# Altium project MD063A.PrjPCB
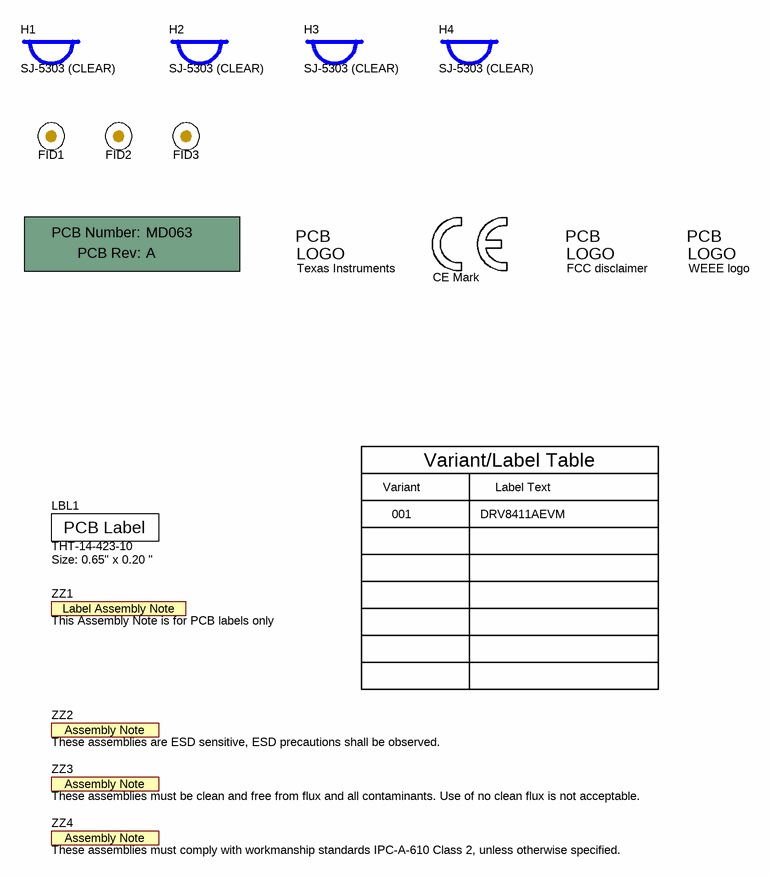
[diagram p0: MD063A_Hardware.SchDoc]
CopyrightYear: 2023; EVM_orderable: DRV8411AEVM; PCB_Layout: Pablo Armet; PCB_Rev: A; PRJ_Customer: Public Release; PRJ_Engineer: Pablo Armet; PRJ_Number: MD063; PRJ_Title: DRV8411AEVM; SCH_Rev: A; SVN: 0; TechSupport: http://www.ti.com/support; TID: N/A
3 sheets, 163 parts. Net scope: global (net labels, ports and power ports of the same name join across sheets).
Board file: MD063A_PCB.PcbDoc
Sheets:
  MD063A_Hardware.SchDoc
  MD063A_Sch.SchDoc
  ezFET.SchDoc

## Sheet MD063A_Hardware.SchDoc
size 431 x 279 mm; Date: Not shown in title block; ApprovedBy: Not shown in title block; CheckedBy: Not shown in title block; Author: Not shown in title block; CompanyName: Not shown in title block; Engineer: Not shown in title block; Organization: Not shown in title block; Address1: Not shown in title block; Address2: Not shown in title block; Address3: Not shown in title block; Address4: Not shown in title block; DocumentNumber: 3; Revision: Use project parameter SCH_Rev; SheetNumber: 3; SheetTotal: 3; PageSetup: Record=PageOptions¦CenterHorizontal=True¦CenterVertical=True¦PrintScale=1.00¦XCorrection=1.00¦YCorrection=1.00¦PrintKind=0¦BorderSize=5000000¦LeftOffset=0¦BottomOffset=0¦Orientation=2¦PaperLength=1000¦PaperWidth=1000¦Scale=100¦PaperSource=15¦PrintQuality=600¦MediaType=1¦DitherType=10¦PaperKind=Letter¦PrintScaleMode=1

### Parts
!PCB1  Printed Circuit Board  (value not drawn)  (mechanical)
FID1  Fiducial  [Fiducial10-20]  (value not drawn)
FID2  Fiducial  [Fiducial10-20]  (value not drawn)
FID3  Fiducial  [Fiducial10-20]  (value not drawn)
H1  SJ-5303 (CLEAR)  [Bumpon_SJ5003Transparent]
H2  SJ-5303 (CLEAR)  [Bumpon_SJ5003Transparent]
H3  SJ-5303 (CLEAR)  [Bumpon_SJ5003Transparent]
H4  SJ-5303 (CLEAR)  [Bumpon_SJ5003Transparent]
LBL1  THT-14-423-10  Note: Size: 0.65" x 0.20 "  [Label_650x200]
Logo1  Texas Instruments  [TI_Stacked_Overlay_Small]  (no BOM)
Logo2  CE Mark  [CE_Mark_5mm]  (no BOM)
Logo3  FCC disclaimer  [FCC_disclaimer]  (no BOM)
Logo4  WEEE logo  [WEEE_Minimum]  (no BOM)
ZZ1  This Assembly Note is for PCB labels only  [AssemblyNoteLabel]  (no BOM)
ZZ2  These assemblies are ESD sensitive, ESD precautions shall be observed.  [AssemblyNote]  (no BOM)
ZZ3  These assemblies must be clean and free from flux and all contaminants. Use of no clean flux is not acceptable.  [AssemblyNote]  (no BOM)
ZZ4  These assemblies must comply with workmanship standards IPC-A-610 Class 2, unless otherwise specified.  [AssemblyNote]  (no BOM)

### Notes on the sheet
- Variant
- Variant/Label Table
- Label Text
- 001
- DRV8411AEVM

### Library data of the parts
!PCB1 = CMP-0003618-2: Manufacturer: Any; PartNumber: MD063
FID1-FID3 = CMP-0077181-1: Fiducial mark.  There is nothing to buy or mount.
H1-H4 = CMP-0003620-1: Bumpon, Hemisphere, 0.44 X 0.20, Clear; Manufacturer: 3M
LBL1 = CMP-0003625-1: Thermal Transfer Printable Labels, 0.650" W x 0.200" H - 10,000 per roll; Manufacturer: Brady; CompType: Label
Logo1 = CMP-0074838-1: Texas Instrument Corporate Signature; SymbolCreator: a0412235; Lib Reference: TI_Logo; Library Reference: Logo
Logo2 = CMP-0074844-1: SymbolCreator: a0412235
Logo3 = CMP-0074847-1: FCC_disclaimer; Library Reference: Logo
Logo4 = CMP-0074769-3: Manufacturer: Texas Instruments; CompType: IC; AEC Category: Q200
ZZ1 = CMP-0003616-3
ZZ2 = CMP-0077236-1
ZZ3 = CMP-0077237-1
ZZ4 = CMP-0077238-1

## Sheet MD063A_Sch.SchDoc
size 431 x 279 mm; Date: Not shown in title block; ApprovedBy: Not shown in title block; CheckedBy: Not shown in title block; Author: Not shown in title block; CompanyName: Not shown in title block; Engineer: Not shown in title block; Organization: Not shown in title block; Address1: Not shown in title block; Address2: Not shown in title block; Address3: Not shown in title block; Address4: Not shown in title block; DocumentNumber: 2; Revision: Use project parameter SCH_Rev; SheetNumber: 2; SheetTotal: 3; PageSetup: Record=PageOptions¦CenterHorizontal=True¦CenterVertical=True¦PrintScale=1.00¦XCorrection=1.00¦YCorrection=1.00¦PrintKind=0¦BorderSize=5000000¦LeftOffset=0¦BottomOffset=0¦Orientation=2¦PaperLength=1000¦PaperWidth=1000¦Scale=100¦PaperSource=15¦PrintQuality=600¦MediaType=1¦DitherType=10¦PaperKind=Letter¦PrintScaleMode=1
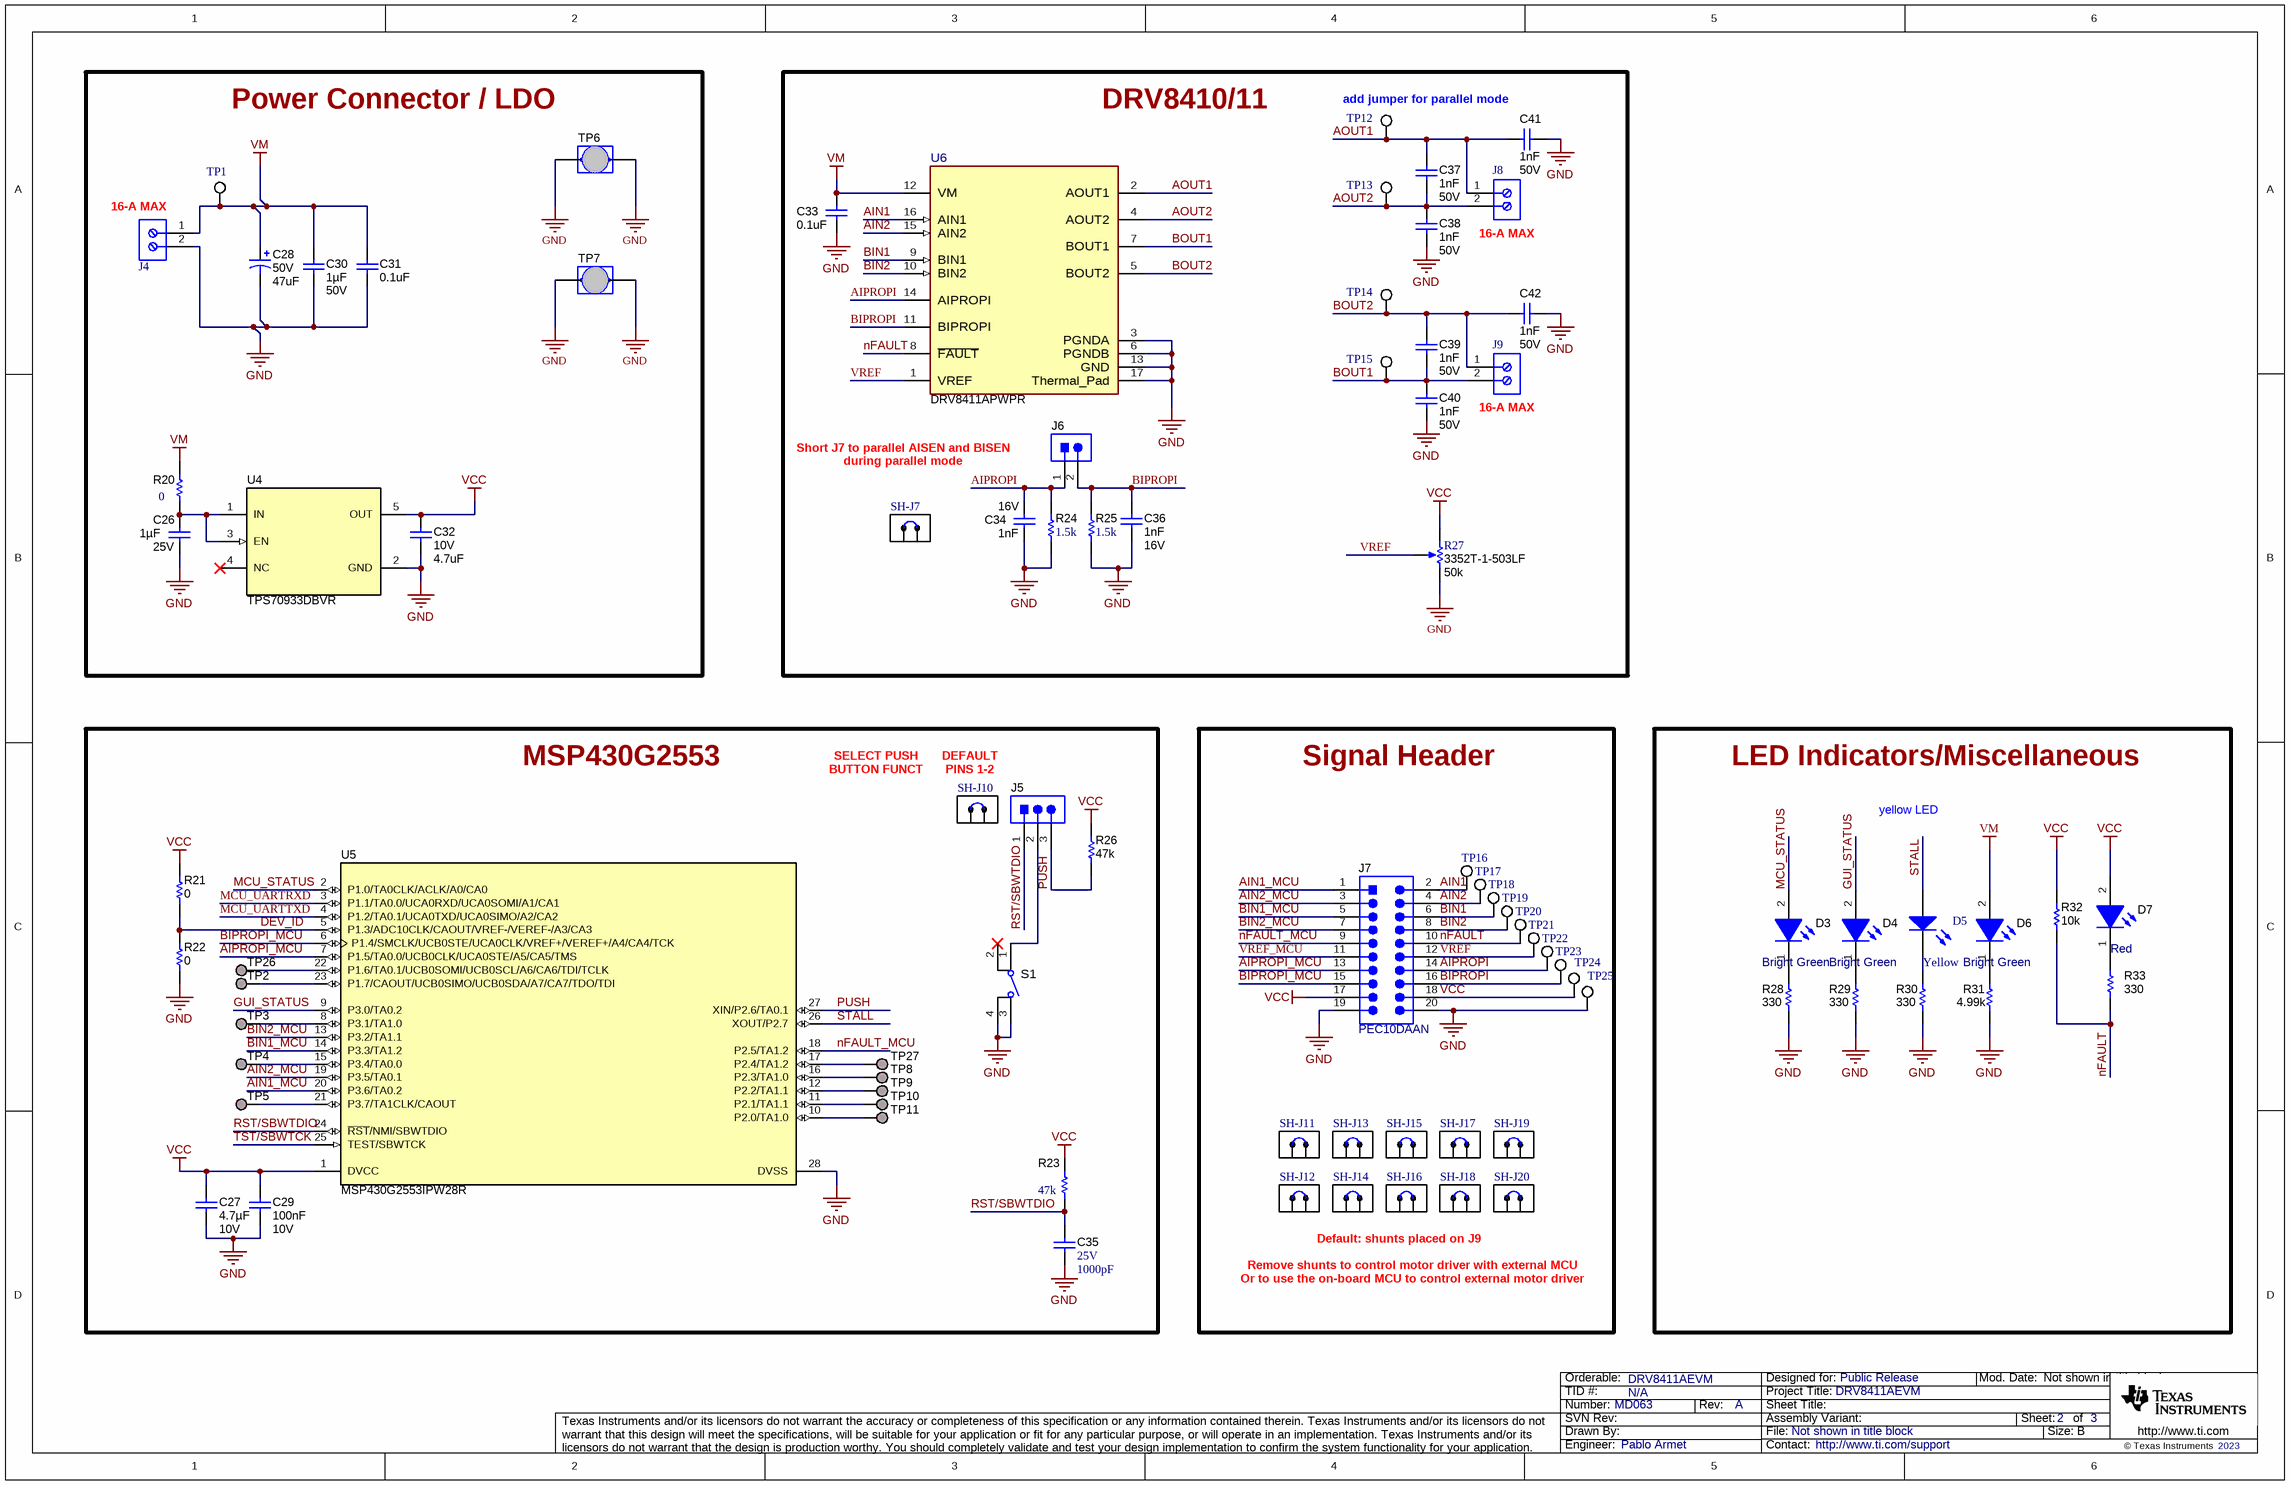
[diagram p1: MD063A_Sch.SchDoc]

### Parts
C26  Cap_F: 1µF  VDC_V: 25V  [0603]  (hidden comment: 885012206076)
C27  Cap_F: 4.7µF  VDC_V: 10V  [0805L]  (hidden comment: 885012207025)
C28  VDC_V: 50V  ValueDisplayed: 47uF  [WCAP-ASLI_630x770]  (hidden comment: 865080645012)
C29  Cap_F: 100nF  VDC_V: 10V  [0603]  (hidden comment: 885012206020)
C30  Cap_F: 1µF  VDC_V: 50V  [0805L]  (hidden comment: 885012207103)
C31  ValueDisplayed: 0.1uF  [0603L]  (hidden comment: 885012206095)
C32  VDC_V: 10V  ValueDisplayed: 4.7uF  [0603]  (hidden comment: GRM188R61A475ME15)
C33  ValueDisplayed: 0.1uF  [0603L]  (hidden comment: 885012206095)
C34  Cap_F: 1nF  VDC_V: 16V  [0603L]  (hidden comment: 885012206034)
C35  VDC_V: 25V  ValueDisplayed: 1000pF  [0603S]  (hidden comment: GRM1885C1E102JA01D)
C36  Cap_F: 1nF  VDC_V: 16V  [0603L]  (hidden comment: 885012206034)
C37  Cap_F: 1nF  VDC_V: 50V  [0603L]  (hidden comment: 885012206083)
C38  Cap_F: 1nF  VDC_V: 50V  [0603L]  (hidden comment: 885012206083)
C39  Cap_F: 1nF  VDC_V: 50V  [0603L]  (hidden comment: 885012206083)
C40  Cap_F: 1nF  VDC_V: 50V  [0603L]  (hidden comment: 885012206083)
C41  Cap_F: 1nF  VDC_V: 50V  [0603L]  (hidden comment: 885012206083)
C42  Cap_F: 1nF  VDC_V: 50V  [0603L]  (hidden comment: 885012206083)
D3  value Bright Green  [WL-SMCW_Green_0805]  (hidden comment: 150080VS75000)
D4  value Bright Green  [WL-SMCW_Green_0805]  (hidden comment: 150080VS75000)
D5  Yellow  [0805_A]
D6  value Bright Green  [WL-SMCW_Green_0805]  (hidden comment: 150080VS75000)
D7  value Red  [WL-SMCW_RED_0805]  (hidden comment: 150080SS75000)
J4  691101710002  [691101710002]  (value not drawn)
J5  61300311121  [WURTH_61300311121]  (value not drawn)
J6  61300211121  [WURTH_61300211121]  (value not drawn)
J7  PEC10DAAN  [SULLINS_PEC10DAAN]
J8  691101710002  [691101710002]  (value not drawn)
J9  691101710002  [691101710002]  (value not drawn)
R20  ValueDisplayed: 0  [0603L]  (hidden comment: ERJ-3GEY0R00V)
R21  value 0  [0603L]  (hidden comment: CRCW06030000Z0EA)
R22  value 0  [0603L]  (hidden comment: CRCW06030000Z0EA)
R23  ValueDisplayed: 47k  [0603S]  (hidden comment: RC0603JR-0747KL)
R24  ValueDisplayed: 1.5k  [0603S]  (hidden comment: CRCW06031K50JNEA)
R25  ValueDisplayed: 1.5k  [0603S]  (hidden comment: CRCW06031K50JNEA)
R26  value 47k  [0603L]  (hidden comment: CRCW060347K0JNEA)
R27  3352T-1-503LF  value 50k  [Bourns_3352T]
R28  value 330  [0603L]  (hidden comment: CRCW0603330RJNEA)
R29  value 330  [0603L]  (hidden comment: CRCW0603330RJNEA)
R30  value 330  [0603L]  (hidden comment: CRCW0603330RJNEA)
R31  value 4.99k  [0603L]  (hidden comment: CRCW06034K99FKEA)
R32  ValueDisplayed: 10k  [0603L]  (hidden comment: CRCW060310K0JNEA)
R33  value 330  [0603L]  (hidden comment: CRCW0603330RJNEA)
S1  FSM4JSMA  [SW_FSM4JSMA]  (value not drawn)
SH-J7  60900213421  [Wurth_60900213421]  (value not drawn)
SH-J10  60900213421  [Wurth_60900213421]  (value not drawn)
SH-J11  60900213421  [Wurth_60900213421]  (value not drawn)
SH-J12  60900213421  [Wurth_60900213421]  (value not drawn)
SH-J13  60900213421  [Wurth_60900213421]  (value not drawn)
SH-J14  60900213421  [Wurth_60900213421]  (value not drawn)
SH-J15  60900213421  [Wurth_60900213421]  (value not drawn)
SH-J16  60900213421  [Wurth_60900213421]  (value not drawn)
SH-J17  60900213421  [Wurth_60900213421]  (value not drawn)
SH-J18  60900213421  [Wurth_60900213421]  (value not drawn)
SH-J19  60900213421  [Wurth_60900213421]  (value not drawn)
SH-J20  60900213421  [Wurth_60900213421]  (value not drawn)
TP1  5016  [Testpoint_Keystone_Compact]  (value not drawn)
TP2  TP_H0.45P0.75  [TP_H045P075]  (value not drawn)  (no BOM)
TP3  TP_H0.45P0.75  [TP_H045P075]  (value not drawn)  (no BOM)
TP4  TP_H0.45P0.75  [TP_H045P075]  (value not drawn)  (no BOM)
TP5  TP_H0.45P0.75  [TP_H045P075]  (value not drawn)  (no BOM)
TP6  CMP-0075110-1  [Harwin_D3082-05]  (value not drawn)
TP7  CMP-0075110-1  [Harwin_D3082-05]  (value not drawn)
TP8  TP_H0.45P0.75  [TP_H045P075]  (value not drawn)  (no BOM)
TP9  TP_H0.45P0.75  [TP_H045P075]  (value not drawn)  (no BOM)
TP10  TP_H0.45P0.75  [TP_H045P075]  (value not drawn)  (no BOM)
TP11  TP_H0.45P0.75  [TP_H045P075]  (value not drawn)  (no BOM)
TP12  5016  [Testpoint_Keystone_Compact]  (value not drawn)
TP13  5016  [Testpoint_Keystone_Compact]  (value not drawn)
TP14  5016  [Testpoint_Keystone_Compact]  (value not drawn)
TP15  5016  [Testpoint_Keystone_Compact]  (value not drawn)
TP16  5002  [Keystone5002]  (value not drawn)
TP17  5002  [Keystone5002]  (value not drawn)
TP18  5002  [Keystone5002]  (value not drawn)
TP19  5002  [Keystone5002]  (value not drawn)
TP20  5002  [Keystone5002]  (value not drawn)
TP21  5002  [Keystone5002]  (value not drawn)
TP22  5002  [Keystone5002]  (value not drawn)
TP23  5002  [Keystone5002]  (value not drawn)
TP24  5002  [Keystone5002]  (value not drawn)
TP25  5002  [Keystone5002]  (value not drawn)
TP26  TP_H0.45P0.75  [TP_H045P075]  (value not drawn)  (no BOM)
TP27  TP_H0.45P0.75  [TP_H045P075]  (value not drawn)  (no BOM)
U4  TPS70933DBVR  [DBV0005A_N]
U5  MSP430G2553IPW28R  [PW0028A_N]
U6  DRV8411APWPR  [PWP0016C-MFG]

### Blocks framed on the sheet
Power Connector / LDO: C26 C28 C30-C32 J4 R20 TP1 TP6 TP7 U4
DRV8410/11: C33 C34 C36-C42 J6 J8 J9 R24 R25 R27 SH-J7 TP12-TP15 U6
MSP430G2553: C27 C29 C35 J5 R21-R23 R26 S1 SH-J10 TP2-TP5 TP8-TP11 TP26 TP27 U5
Signal Header: J7 SH-J11-SH-J20 TP16-TP25
LED Indicators/Miscellaneous: D3-D7 R28-R33

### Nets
GND: C26.2 C27.2 C28.2(-) C29.2 C30.2 C31.2 C32.2 C33.2 C34.2 C35.2 C36.2 C38.2 C40.2 C41.2 C42.2 J4.2 J7.19 J7.20 R22.1 R24.1 R25.1 R27.3(CW) R28.1 R29.1 R30.1 R31.1 S1.3 S1.4 TP6.1 TP6.2 TP7.1 TP7.2 TP25.1 U4.2(GND) U5.28(DVSS) U6.3(PGNDA) U6.6(PGNDB) U6.13(GND) U6.17(Thermal_Pad)
VCC: C27.1 C29.1 C32.1 D7.2(A) J7.17 J7.18 R21.2 R23.2 R26.2 R27.1(CCW) R32.2 TP24.1 U4.5(OUT) U5.1(DVCC)
VM: C28.1(+) C30.1 C31.1 C33.1 D6.2(A) J4.1 R20.2 TP1.1 U6.12(VM)
AIN1: J7.2 TP16.1 U6.16(AIN1)
AIN1_MCU: J7.1 U5.20(P3.6/TA0.2)
AIN2: J7.4 TP17.1 U6.15(AIN2)
AIN2_MCU: J7.3 U5.19(P3.5/TA0.1)
AIPROPI: C34.1 J6.1 J7.14 R24.2 TP22.1 U6.14(AIPROPI)
AIPROPI_MCU: J7.13 U5.7(P1.5/TA0.0/UCB0CLK/UCA0STE/A5/CA5/TMS)
AOUT1: C37.1 C41.1 J8.1 TP12.1 U6.2(AOUT1)
AOUT2: C37.2 C38.1 J8.2 TP13.1 U6.4(AOUT2)
BIN1: J7.6 TP18.1 U6.9(BIN1)
BIN1_MCU: J7.5 U5.14(P3.3/TA1.2)
BIN2: J7.8 TP19.1 U6.10(BIN2)
BIN2_MCU: J7.7 U5.13(P3.2/TA1.1)
BIPROPI: C36.1 J6.2 J7.16 R25.2 TP23.1 U6.11(BIPROPI)
BIPROPI_MCU: J7.15 U5.6(P1.4/SMCLK/UCB0STE/UCA0CLK/VREF+/VEREF+/A4/CA4/TCK)
BOUT1: C39.2 C40.1 J9.2 TP15.1 U6.7(BOUT1)
BOUT2: C39.1 C42.1 J9.1 TP14.1 U6.5(BOUT2)
DEV_ID: R21.1 R22.2 U5.5(P1.3/ADC10CLK/CAOUT/VREF-/VEREF-/A3/CA3)
GUI_STATUS: D4.2(A) U5.9(P3.0/TA0.2)
MCU_STATUS: D3.2(A) U5.2(P1.0/TA0CLK/ACLK/A0/CA0)
MCU_UARTRXD: U5.3(P1.1/TA0.0/UCA0RXD/UCA0SOMI/A1/CA1)
MCU_UARTTXD: U5.4(P1.2/TA0.1/UCA0TXD/UCA0SIMO/A2/CA2)
nFAULT: J7.10 R32.1 R33.1 TP20.1 U6.8(~{FAULT})
nFAULT_MCU: J7.9 U5.18(P2.5/TA1.2)
PUSH: J5.3 R26.1 U5.27(XIN/P2.6/TA0.1)
RST/SBWTDIO: C35.1 J5.1 R23.1 U5.24(~{RST}/NMI/SBWTDIO)
STALL: D5.2(A) U5.26(XOUT/P2.7)
TST/SBWTCK: U5.25(TEST/SBWTCK)
VREF: J7.12 R27.2(WIPER) TP21.1 U6.1(VREF)
VREF_MCU: J7.11
NetC26_1: C26.1 R20.1 U4.1(IN) U4.3(EN)
NetD3_1: D3.1(K) R28.2
NetD4_1: D4.1(K) R29.2
NetD5_1: D5.1(K) R30.2
NetD6_1: D6.1(K) R31.2
NetD7_1: D7.1(K) R33.2
NetJ5_2: J5.2 S1.1
NetTP2_1: TP2.1 U5.23(P1.7/CAOUT/UCB0SIMO/UCB0SDA/A7/CA7/TDO/TDI)
NetTP3_1: TP3.1 U5.8(P3.1/TA1.0)
NetTP4_1: TP4.1 U5.15(P3.4/TA0.0)
NetTP5_1: TP5.1 U5.21(P3.7/TA1CLK/CAOUT)
NetTP8_1: TP8.1 U5.16(P2.3/TA1.0)
NetTP9_1: TP9.1 U5.12(P2.2/TA1.1)
NetTP10_1: TP10.1 U5.11(P2.1/TA1.1)
NetTP11_1: TP11.1 U5.10(P2.0/TA1.0)
NetTP26_1: TP26.1 U5.22(P1.6/TA0.1/UCB0SOMI/UCB0SCL/A6/CA6/TDI/TCLK)
NetTP27_1: TP27.1 U5.17(P2.4/TA1.2)

Not connected (* = marked no-connect by the designer): S1 2*; U4 4(NC)*

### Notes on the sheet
- (near TP12) add jumper for parallel mode
- (near J4) 16-A MAX
- (near J8) 16-A MAX
- (near J9) 16-A MAX
- Short J7 to parallel AISEN and BISEN
- during parallel mode
- SELECT PUSH
- BUTTON FUNCT
- DEFAULT
- (near SH-J10) PINS 1-2
- yellow LED
- Default: shunts placed on J9
- Remove shunts to control motor driver with external MCU
- Or to use the on-board MCU to control external motor driver

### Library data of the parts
C26 = CMP-0006833-4: CAP, CERM, 1 uF, 25 V, +/- 10%, X7R, 0603; Manufacturer: Wurth Elektronik; TaMin_C: -55°C; Polarized: N; SizeAreaWB_mm2: 4.68; Value1: Unknown; U/M: EA; Value: 1uF; TaMax_C: 125°C; SizeZ_mm: 1; SizeX_mm: 1.6; SizeY_mm: 0.8; SizeArea_mm2: 1.28; AEC Category: Q200
C27 = CMP-0007690-2: CAP, CERM, 4.7 uF, 10 V, +/- 10%, X7R, 0805; Manufacturer: Wurth Elektronik; TaMin_C: -55°C; Polarized: N; SizeAreaWB_mm2: 6.75; Value1: Unknown; U/M: EA; Value: 4.7uF; TaMax_C: 125°C; SizeZ_mm: 1.45; SizeX_mm: 2; SizeY_mm: 1.25; Cap_Case: 0805; SizeArea_mm2: 2.5; AEC Category: Q200
C28 = CMP-0011161-2: CAP, AL, 47 uF, 50 V, +/- 20%, SMD; Manufacturer: Wurth Elektronik; TaMin_C: -55°C; Polarized: Y; SizeAreaWB_mm2: 79.98; Value1: Unknown; U/M: EA; Value: 47uF; TaMax_C: 105°C; SizeZ_mm: 7.7; SizeX_mm: 7.3; SizeY_mm: 6.6; Cap_Case: 6.3x7.7mm; SizeArea_mm2: 48.18; CompType: Capacitor; AEC Qualified: N; Cap_F: 47µF; IRMS_A: 230mA; AEC Category: Q200
C29 = CMP-0064931-4: CAP, CERM, 0.1 uF, 10 V,+/- 10%, X7R, 0603; Manufacturer: Wurth Elektronik; TaMin_C: -55°C; Polarized: N; SizeAreaWB_mm2: 4.68; Value1: Unknown; U/M: EA; Value: 0.1uF; TaMax_C: 125°C; SizeZ_mm: 1; SizeX_mm: 1.6; SizeY_mm: 0.8; SizeArea_mm2: 1.28; AEC Category: Q200
C30 = CMP-0007696-2: CAP, CERM, 1 uF, 50 V, +/- 10%, X7R, 0805; Manufacturer: Wurth Elektronik; TaMin_C: -55°C; Polarized: N; SizeAreaWB_mm2: 6.75; Value1: Unknown; U/M: EA; Value: 1uF; TaMax_C: 125°C; SizeZ_mm: 1.45; SizeX_mm: 2; SizeY_mm: 1.25; Cap_Case: 0805; SizeArea_mm2: 2.5; AEC Category: Q200
C31 C33 = CMP-0006837-4: CAP, CERM, 0.1 uF, 50 V, +/- 10%, X7R, 0603; Manufacturer: Wurth Elektronik; Polarized: N; Value: 0.1uF; U/M: EA; Cap_F: 100nF; Value1: Unknown; VDC_V: 50V; TaMin_C: -55°C; TaMax_C: 125°C; Cap_Case: 0603; SizeArea_mm2: 1.28; SizeAreaWB_mm2: 4.68; SizeX_mm: 1.6; SizeY_mm: 0.8; SizeZ_mm: 1; AEC Category: Q200
C32 = CMP-0007330-5: CAP, CERM, 4.7 uF, 10 V, +/- 20%, X5R, 0603; Manufacturer: MuRata; TaMin_C: -55°C; Polarized: N; SizeAreaWB_mm2: 4.68; Value1: Unknown; U/M: EA; Value: 4.7uF; TaMax_C: 85°C; SizeZ_mm: 1; SizeX_mm: 1.6; SizeY_mm: 0.8; SizeArea_mm2: 1.28; Cap_F: 4.7µF; AEC Category: Q200
C34 C36 = CMP-0006826-4: CAP, CERM, 1000 pF, 16 V, +/- 10%, X7R, 0603; Manufacturer: Wurth Elektronik; TaMin_C: -55°C; Polarized: N; SizeAreaWB_mm2: 4.68; Value1: Unknown; U/M: EA; Value: 1000pF; TaMax_C: 125°C; SizeZ_mm: 1; SizeX_mm: 1.6; SizeY_mm: 0.8; Cap_Case: 0603; SizeArea_mm2: 1.28; AEC Category: Q200
C35 = CMP-0007159-4: CAP, CERM, 1000 pF, 25 V, +/- 5%, C0G/NP0, 0603; Manufacturer: MuRata; TaMin_C: -55°C; Polarized: N; SizeAreaWB_mm2: 4.68; Value1: Unknown; U/M: EA; Value: 1000pF; TaMax_C: 125°C; SizeZ_mm: 1; SizeX_mm: 1.6; SizeY_mm: 0.8; Cap_Case: 0603; SizeArea_mm2: 1.28; Cap_F: 1nF; AEC Category: Q200
C37-C42 = CMP-0064933-4: CAP, CERM, 1000 pF, 50 V,+/- 10%, X7R, 0603; Manufacturer: Wurth Elektronik; TaMin_C: -55°C; Polarized: N; SizeAreaWB_mm2: 4.68; Value1: Unknown; U/M: EA; Value: 1000pF; TaMax_C: 125°C; SizeZ_mm: 1; SizeX_mm: 1.6; SizeY_mm: 0.8; Cap_Case: 0603; SizeArea_mm2: 1.28; AEC Category: Q200
D3 D4 D6 = CMP-0002960-2: LED, Bright Green, SMD; Manufacturer: Wurth Elektronik; Io_A: 20mA; Power_TotalModule: 72mW; Vr_V: 5V; Tjmax_C: 85°C; Value1: 0.072W; U/M: EA; Angle: 140; Vf_V: 2V; Type: AlInGaP
D5 = CMP-1426-00012-1: SMD mono-color Chip LED, WL-SMCW, Yellow; Manufacturer: Wuerth Elektronik; PartNumber: 150080YS75000
D7 = CMP-0002951-3: LED, Red, SMD; Manufacturer: Wurth Elektronik; Type: AlInGaP; Angle: 140; Vr_V: 5V; Ir_A: 25µA; Vf_V: 1.9V; Value1: 0.072W; Tjmax_C: 85°C; Io_A: 30mA; Power_TotalModule: 72mW
J4 J8 J9 = CMP-1502-03256-1: Series 101 - 5.00 mm Horizontal Entry Modular with Pressure Clamp WR-TBL, 2 pin; Manufacturer: Wurth Elektronik; Pin Number: 2; Pitch: 5.00mm
J5 = CMP-0054796-4: Header, 2.54 mm, 3x1, Gold, TH; Manufacturer: Wurth Elektronik; Green_Lifecycle: Active; Green_REACh: Passed; CT: FALSE; CNHeader: TRUE
J6 = CMP-0054794-2: Header, 2.54 mm, 2x1, Gold, TH; Manufacturer: Wurth Elektronik; Shrouded: N; Gender: Male; Green_REACh: Passed; Pitch_mm: 2.54; Green_Lifecycle: Active; Row_Count: 1; Cert_UL: Y
J7 = CMP-0054623-2: Header, 2.54mm, 10x2, Tin, TH; Manufacturer: Sullins Connector Solutions; Current_A: 3A; Green_Lifecycle: Not Set; Shrouded: N; Gender: Male; Green_REACh: Incomplete; Row_Count: 2; RowSpacing_mm: 2.54; Cert_UL: Y
R20 = CMP-0025874-4: RES, 0, 5%, 0.1 W, AEC-Q200 Grade 0, 0603; Manufacturer: Panasonic; Value: 0; Value_Code: 0000; Power_W: 100mW; Value2: 0.1W; VDC_V: 50V; TempCo: 600 ppm/C; EIA_Code: E24; SizeArea_mm2: 1.28; SizeX_mm: 1.6; SizeY_mm: 0.8; SizeZ_mm: 1; AEC Category: Q200; AEC Qualified: Y; SizeAreaWB_mm2: 4.68
R21 R22 = CMP-0025697-4: RES, 0, 5%, 0.1 W, AEC-Q200 Grade 0, 0603; Manufacturer: Vishay-Dale; Value_Code: 0000; Power_W: 100mW; Value2: 0.1W; VDC_V: 75V; TempCo: 200 ppm/C; EIA_Code: E24; AEC Category: Q200; AEC Qualified: Y; SizeArea_mm2: 1.28; SizeX_mm: 1.6; SizeY_mm: 0.8; SizeZ_mm: 1
R23 = CMP-0025925-5: RES, 47 k, 5%, 0.1 W, 0603; Manufacturer: Yageo; Power_W: 100mW; TempCo: 100 ppm/C; Value_Code: 47k0; Value: 47k; EIA_Code: E24; SizeX_mm: 1.6; SizeY_mm: 0.8; SizeZ_mm: 1; Value2: 0.1W; SizeArea_mm2: 1.28; AEC Qualified: N; VDC_V: 75V; AEC Category: Q200; SizeAreaWB_mm2: 4.68
R24 R25 = CMP-0025733-4: RES, 1.5 k, 5%, 0.1 W, AEC-Q200 Grade 0, 0603; Manufacturer: Vishay-Dale; Power_W: 100mW; TempCo: 200 ppm/C; Value_Code: 1k50; Value: 1.5k; EIA_Code: E24; SizeX_mm: 1.6; SizeY_mm: 0.8; SizeZ_mm: 1; Value2: 0.1W; SizeArea_mm2: 1.28; AEC Qualified: Y; VDC_V: 75V; AEC Category: Q200; AEC Grade: 0
R26 = CMP-0025814-4: RES, 47 k, 5%, 0.1 W, AEC-Q200 Grade 0, 0603; Manufacturer: Vishay-Dale; Value_Code: 47k0; Power_W: 100mW; Value2: 0.1W; VDC_V: 75V; TempCo: 200 ppm/C; EIA_Code: E24; AEC Category: Q200; AEC Qualified: Y; AEC Grade: 0; SizeArea_mm2: 1.28; SizeX_mm: 1.6; SizeY_mm: 0.8; SizeZ_mm: 1
R27 = CMP-0001777-2: Trimming Potentiometer, 50K, 0.5W, TH; Manufacturer: Bourns; CompType: Trimmer
R28-R30 R33 = CMP-0025785-4: RES, 330, 5%, 0.1 W, AEC-Q200 Grade 0, 0603; Manufacturer: Vishay-Dale; Value_Code: 330R; Power_W: 100mW; Value2: 0.1W; VDC_V: 75V; TempCo: 200 ppm/C; EIA_Code: E24; AEC Category: Q200; AEC Grade: 0; AEC Qualified: Y; SizeArea_mm2: 1.28; SizeX_mm: 1.6; SizeY_mm: 0.8; SizeZ_mm: 1
R31 = CMP-0022458-4: RES, 4.99 k, 1%, 0.1 W, AEC-Q200 Grade 0, 0603; Manufacturer: Vishay-Dale; Value_Code: 4k99; Power_W: 100mW; Value2: 0.1W; VDC_V: 75V; TempCo: 100 ppm/C; EIA_Code: E96; AEC Category: Q200; AEC Qualified: Y; AEC Grade: 0; SizeArea_mm2: 1.28; SizeX_mm: 1.6; SizeY_mm: 0.8; SizeZ_mm: 1
R32 = CMP-0025701-4: RES, 10 k, 5%, 0.1 W, AEC-Q200 Grade 0, 0603; Manufacturer: Vishay-Dale; Value: 10k; Value_Code: 10k0; Power_W: 100mW; Value2: 0.1W; VDC_V: 75V; TempCo: 200 ppm/C; EIA_Code: E24; AEC Category: Q200; AEC Qualified: Y; AEC Grade: 0; SizeArea_mm2: 1.28; SizeX_mm: 1.6; SizeY_mm: 0.8; SizeZ_mm: 1
S1 = CMP-0002134-3: Switch, Tactile, SPST-NO, 0.05A, 12V, SMT; Manufacturer: TE Connectivity; CurrentRating_mA: 50A; PositionCount: 1; SwitchFunction: Off-Mom
SH-J7 SH-J10-SH-J20 = CMP-0003761-2: Shunt, 2.54mm, Gold, Black; Manufacturer: Wurth Elektronik
TP1 TP12-TP15 = CMP-0055153-2: Test Point, Compact, SMT; Manufacturer: Keystone Electronics; CNHeader: FALSE; Green_Lifecycle: Active; Green_REACh: Passed; CT: TRUE
TP2-TP5 TP8-TP11 TP26 TP27 = CMP-0003719-1: Testpoint; Manufacturer: Texas Instruments; CompType: Pad
TP6 TP7 = CMP-0075110-1: 1mm Uninsulated Shorting Plug, 10.16mm spacing, TH; PartNumber: D3082-05; Manufacturer: Harwin; CompType: Jumper Wire; CNHeader: False; Green_Lifecycle: Active; Green_REACh: Passed
TP16-TP25 = CMP-0055139-2: Test Point, Miniature, White, TH; Manufacturer: Keystone Electronics; ContactFinish: Silver; Green_REACh: Passed; CT: TRUE; Green_Lifecycle: Active; CNHeader: FALSE
U4 = CMP-0073793-1: 150-mA, 30-V, Ultra-Low IQ, Wide Input Low-Dropout Regulator with Reverse Current Protection, DBV0005A (SOT-23-5); Alternate PartNumber: TPS70933DBVT; Alternate Manufacturer: Texas Instruments; Green_Lifecycle: Active; SizeAreaWB_mm2: 14.82; Green_REACh: Passed; U/M: EA; SizeZ_mm: 1.45; SizeX_mm: 2.8; SizeY_mm: 2.9; SizeArea_mm2: 8.12; CompType: IC
U5 = CMP-0039449-2: MSP430G2x53, MSP430G2x13 Mixed Signal Microcontroller, PW0028A (TSSOP-28); Manufacturer: Texas Instruments; Temp Sensor: Yes; ADC: 10-bit SAR; SubFamily: Value Line; Timers - 16-bit: 2; ADC Channels: 8; SRAM(B): 512; Frequency(MHz): 16; GPIO: 24; USCI_B (I2C & SPI): 1; Eco-Plan: Green (RoHS & no Sb/Br); AEC Category: Q200; AEC Qualified: N; CompType: IC; SizeAreaWB_mm2: 98.28; SizeArea_mm2: 62.08; SizeX_mm: 6.4; SizeY_mm: 9.7; SizeZ_mm: 1.2
U6 = CMP-0094669-1: Dual H-Bridge Motor Driver with Current Regulation; Manufacturer: Texas Instruments; TJmax_C: +150°C; AEC Qualified: No; Number Of Outputs: 4; Max Supply Voltage: 11V; Min Supply Voltage: 1.65V; Standoff Height: 0.05mm; SizeZ_mm: 1.2mm; TaMax_C: +125°C; TaMin_C: -40°C; Switching Frequency: 100kHz

## Sheet ezFET.SchDoc
size 431 x 279 mm; Date: Not shown in title block; ApprovedBy: Not shown in title block; CheckedBy: Not shown in title block; Author: Not shown in title block; CompanyName: Not shown in title block; Engineer: Not shown in title block; Organization: Not shown in title block; Address1: Not shown in title block; Address2: Not shown in title block; Address3: Not shown in title block; Address4: Not shown in title block; DocumentNumber: 1; Revision: Use project parameter SCH_Rev; SheetNumber: 1; SheetTotal: 3; PageSetup: Record=PageOptions¦CenterHorizontal=True¦CenterVertical=True¦PrintScale=1.00¦XCorrection=1.00¦YCorrection=1.00¦PrintKind=0¦BorderSize=5000000¦LeftOffset=0¦BottomOffset=0¦Orientation=2¦PaperLength=1000¦PaperWidth=1000¦Scale=100¦PaperSource=15¦PrintQuality=600¦MediaType=1¦DitherType=10¦PaperKind=Letter¦PrintScaleMode=1
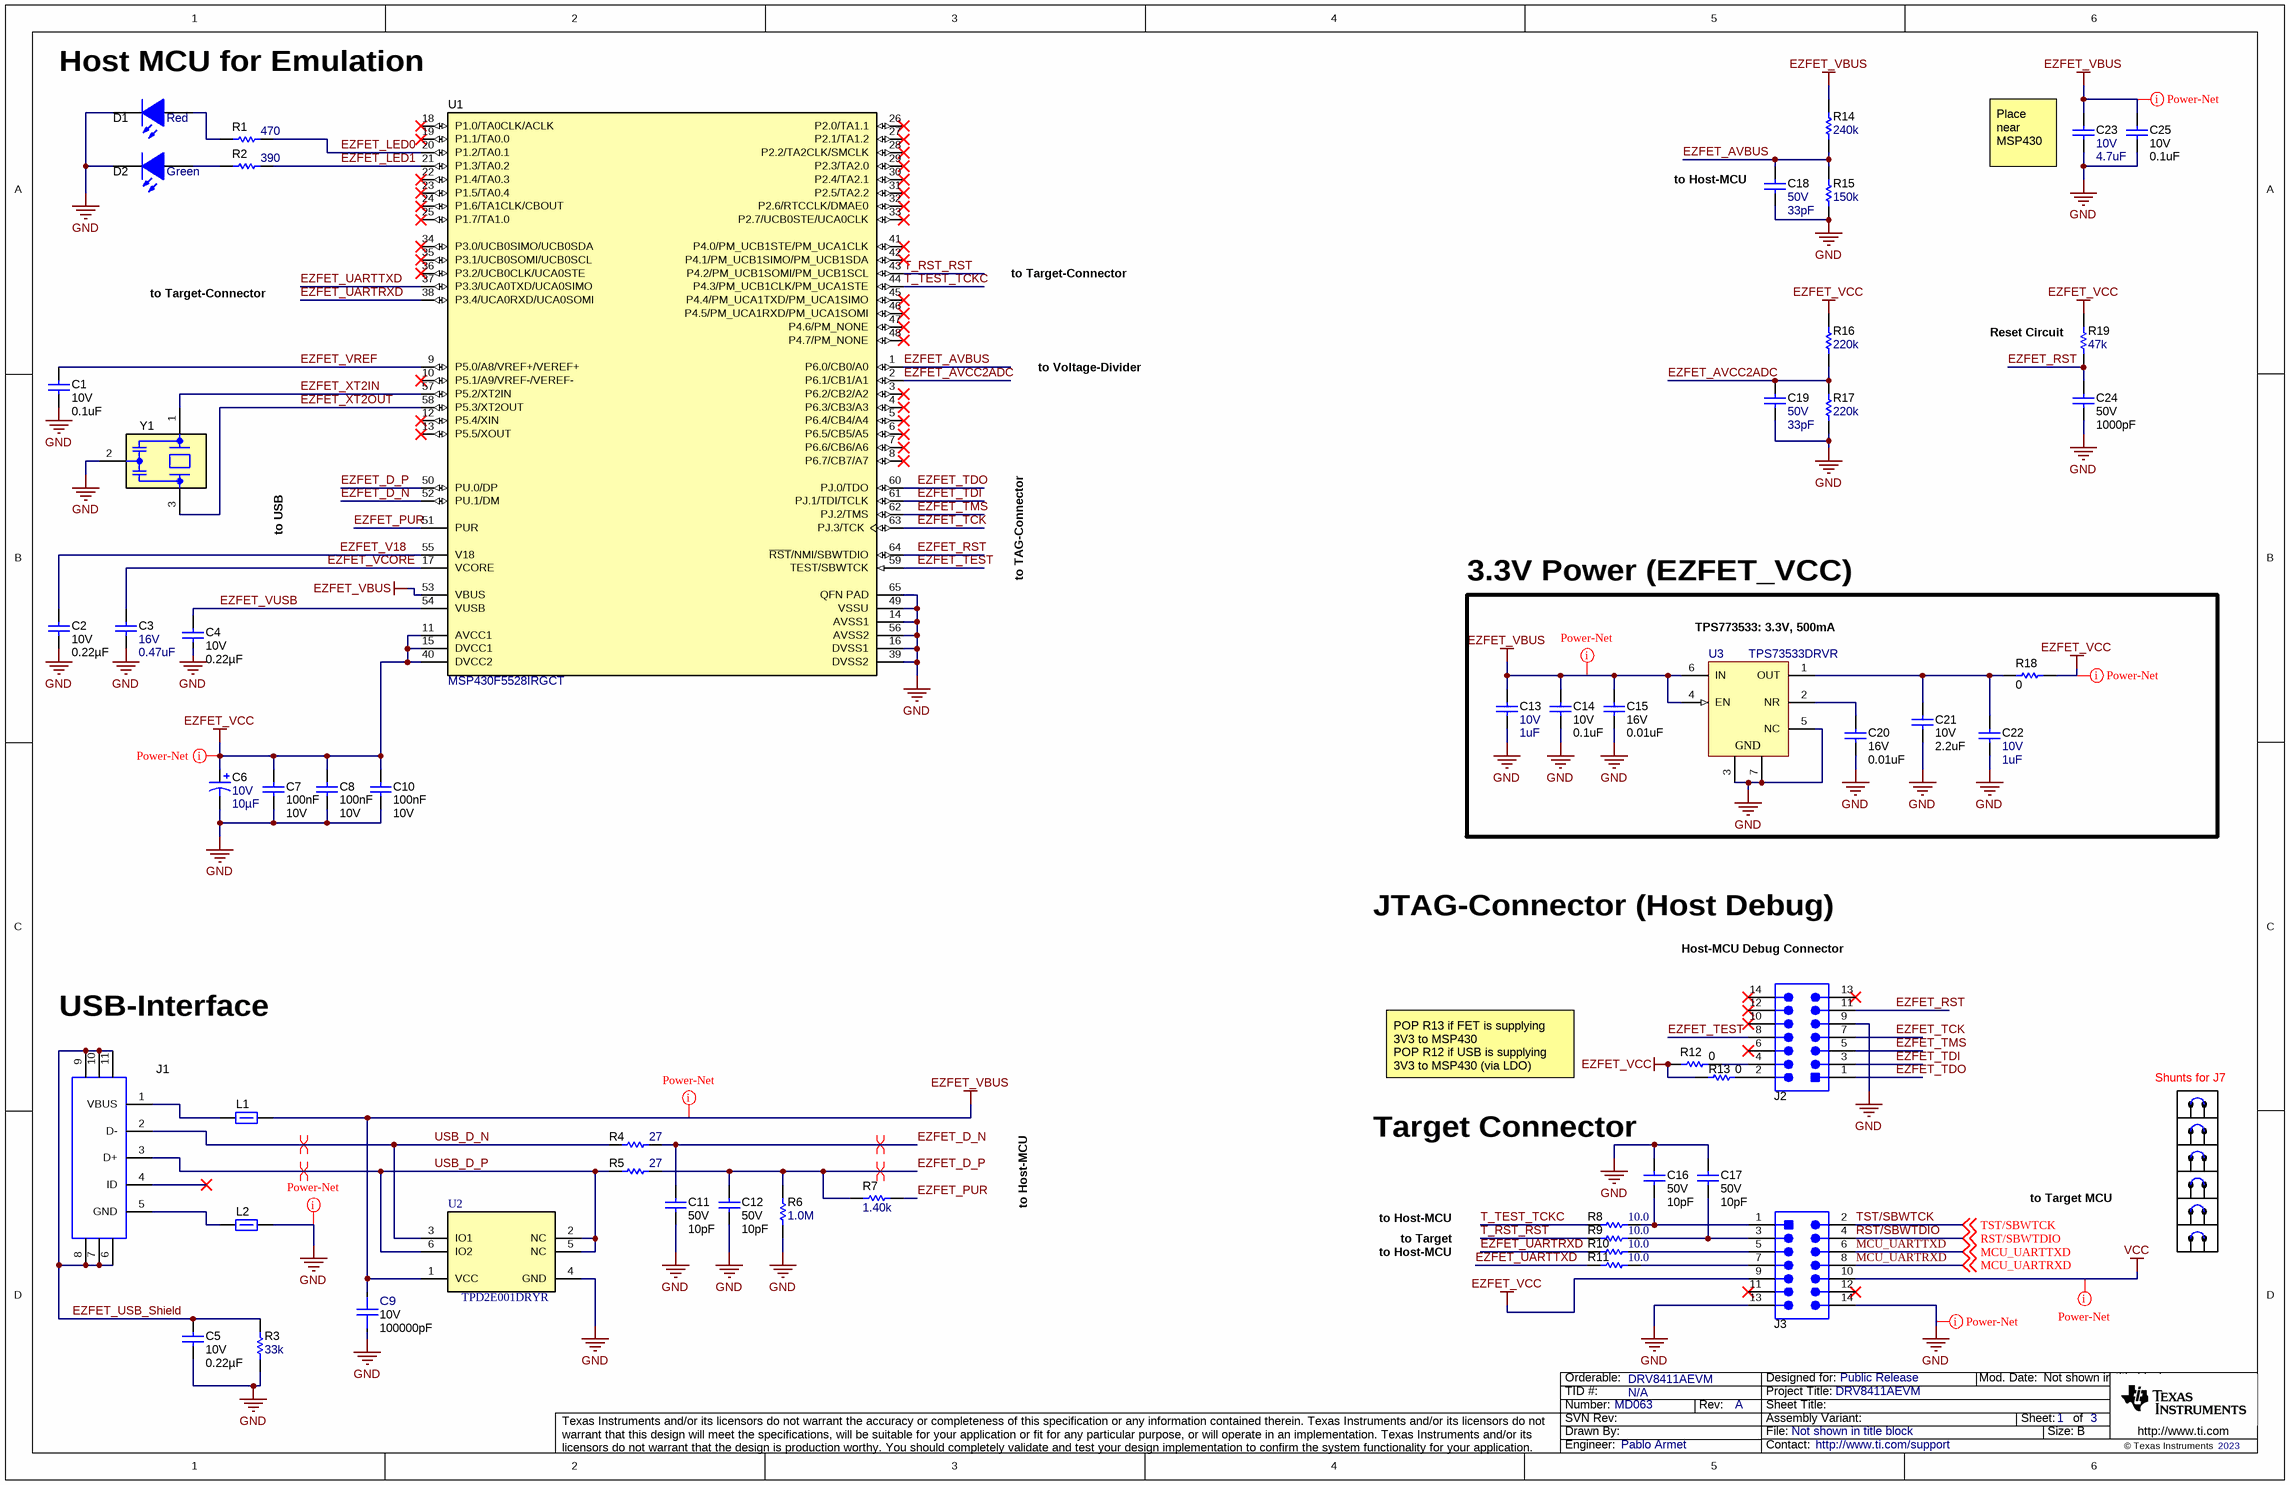
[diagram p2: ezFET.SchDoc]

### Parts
C1  VDC_V: 10V  ValueDisplayed: 0.1uF  [0402L]  (hidden comment: 885012105010)
C2  VDC_V: 10V  ValueDisplayed: 0.22µF  [0402L]  (hidden comment: 885012105011)
C3  VDC_V: 16V  ValueDisplayed: 0.47uF  [0402L]  (hidden comment: GRM155R61C474KE01)
C4  VDC_V: 10V  ValueDisplayed: 0.22µF  [0402L]  (hidden comment: 885012105011)
C5  VDC_V: 10V  ValueDisplayed: 0.22µF  [0402S]  (hidden comment: 885012105011)
C6  VDC_V: 10V  ValueDisplayed: 10µF  [3216-18]  (hidden comment: T520A106M010ATE080)
C7  Cap_F: 100nF  VDC_V: 10V  [0603L]  (hidden comment: 885012206020)
C8  Cap_F: 100nF  VDC_V: 10V  [0603L]  (hidden comment: 885012206020)
C9  VDC_V: 10V  ValueDisplayed: 100000pF  [FP-885012205018_0402-MFG]  (hidden comment: 885012205018)
C10  Cap_F: 100nF  VDC_V: 10V  [0603L]  (hidden comment: 885012206020)
C11  VDC_V: 50V  ValueDisplayed: 10pF  [0402L]  (hidden comment: 885012005055)
C12  VDC_V: 50V  ValueDisplayed: 10pF  [0402L]  (hidden comment: 885012005055)
C13  VDC_V: 10V  ValueDisplayed: 1uF  [0402S]  (hidden comment: 885012105012)
C14  VDC_V: 10V  ValueDisplayed: 0.1uF  [0402S]  (hidden comment: 885012105010)
C15  VDC_V: 16V  ValueDisplayed: 0.01uF  [0402S]  (hidden comment: 885012205031)
C16  VDC_V: 50V  ValueDisplayed: 10pF  [0402L]  (hidden comment: 885012005055)
C17  VDC_V: 50V  ValueDisplayed: 10pF  [0402L]  (hidden comment: 885012005055)
C18  VDC_V: 50V  ValueDisplayed: 33pF  [0402L]  (hidden comment: C1005C0G1H330J050BA)
C19  VDC_V: 50V  ValueDisplayed: 33pF  [0402L]  (hidden comment: C1005C0G1H330J050BA)
C20  VDC_V: 16V  ValueDisplayed: 0.01uF  [0402S]  (hidden comment: 885012205031)
C21  VDC_V: 10V  ValueDisplayed: 2.2uF  [0402S]  (hidden comment: 885012105013)
C22  VDC_V: 10V  ValueDisplayed: 1uF  [0402S]  (hidden comment: 885012105012)
C23  VDC_V: 10V  ValueDisplayed: 4.7uF  [0402S]  (hidden comment: C1005X5R1A475M050BC)
C24  VDC_V: 50V  ValueDisplayed: 1000pF  [0402L]  (hidden comment: 885012205061)
C25  VDC_V: 10V  ValueDisplayed: 0.1uF  [0402S]  (hidden comment: GRM155R61A104KA01D)
D1  value Red  [WL-SMCW_RED]  (hidden comment: 150060RS75000)
D2  value Green  [WL-SMCW_GREEN]  (hidden comment: CMP-0002894-2)
J1  CMP-0055311-1  [Molex_1051640001]  (value not drawn)
J2  61301421121  [Wurth_61301421121]  (value not drawn)
J3  61301421121  [Wurth_61301421121]  (value not drawn)
L1  742792621  [0603L]  (value not drawn)
L2  742792621  [0603L]  (value not drawn)
R1  ValueDisplayed: 470  [0402L]  (hidden comment: CRCW0402470RJNED)
R2  ValueDisplayed: 390  [0402L]  (hidden comment: CRCW0402390RJNED)
R3  ValueDisplayed: 33k  [0402S]  (hidden comment: CRCW040233K0JNED)
R4  ValueDisplayed: 27  [0402L]  (hidden comment: CRCW040227R0JNED)
R5  ValueDisplayed: 27  [0402L]  (hidden comment: CRCW040227R0JNED)
R6  ValueDisplayed: 1.0M  [0402L]  (hidden comment: CRCW04021M00JNED)
R7  ValueDisplayed: 1.40k  [0402L]  (hidden comment: CRCW04021K40FKED)
R8  ValueDisplayed: 10.0  [0402S]  (hidden comment: CRCW040210R0FKED)
R9  ValueDisplayed: 10.0  [0402S]  (hidden comment: CRCW040210R0FKED)
R10  ValueDisplayed: 10.0  [0402S]  (hidden comment: CRCW040210R0FKED)
R11  ValueDisplayed: 10.0  [0402S]  (hidden comment: CRCW040210R0FKED)
R12  value 0  [0402L]  (hidden comment: ERJ-2GE0R00X)
R13  value 0  [0402L]  (hidden comment: ERJ-2GE0R00X)
R14  ValueDisplayed: 240k  [0402L]  (hidden comment: CRCW0402240KFKED)
R15  ValueDisplayed: 150k  [0402L]  (hidden comment: CRCW0402150KFKED)
R16  ValueDisplayed: 220k  [0402L]  (hidden comment: RC0402FR-07220KL)
R17  ValueDisplayed: 220k  [0402L]  (hidden comment: RC0402FR-07220KL)
R18  ValueDisplayed: 0  [0402S]  (hidden comment: CRCW04020000Z0EDHP)
R19  ValueDisplayed: 47k  [0402L]  (hidden comment: CRCW040247K0JNED)
SH-J1  60900213421  [Wurth_60900213421]  (value not drawn)
SH-J2  60900213421  [Wurth_60900213421]  (value not drawn)
SH-J3  60900213421  [Wurth_60900213421]  (value not drawn)
SH-J4  60900213421  [Wurth_60900213421]  (value not drawn)
SH-J5  60900213421  [Wurth_60900213421]  (value not drawn)
SH-J6  60900213421  [Wurth_60900213421]  (value not drawn)
U1  PartNumber: MSP430F5528IRGCT  [RGC0064B]  (hidden comment: CMP-0039269-4)
U2  TPD2E001DRYR  [DRY0006A]
U3  TPS73533DRVR  [DRV0006A]
Y1  CSTNR4M00GH5L000R0  [MuRata_CSTNR]  (value not drawn)

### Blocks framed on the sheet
3.3V Power (EZFET_VCC): C13-C15 C20-C22 R18 U3

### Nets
EZFET_VBUS: C9.2 C13.1 C14.1 C15.1 C23.1 C25.1 L1.2 R14.2 U1.53(VBUS) U2.1(VCC) U3.4(EN) U3.6(IN)
EZFET_VCC: C6.1(+) C7.1 C8.1 C10.1 J3.9 R12.1 R13.1 R16.2 R18.2 R19.2 U1.11(AVCC1) U1.15(DVCC1) U1.40(DVCC2)
GND: C1.2 C2.2 C3.2 C4.2 C5.2 C6.2(-) C7.2 C8.2 C9.1 C10.2 C11.2 C12.2 C13.2 C14.2 C15.2 C16.1 C17.1 C18.2 C19.2 C20.2 C21.2 C22.2 C23.2 C24.2 C25.2 D1.1(K) D2.1(K) J2.9 J3.13 J3.14 L2.2 R3.1 R6.1 R15.1 R17.1 U1.14(AVSS1) U1.16(DVSS1) U1.39(DVSS2) U1.49(VSSU) U1.56(AVSS2) U1.65(QFN_PAD) U2.4(GND) U3.3(GND) U3.5(NC) U3.7(GND) Y1.2(GND)
VCC: J3.10
EZFET_AVBUS: C18.1 R14.1 R15.2 U1.1(P6.0/CB0/A0)
EZFET_AVCC2ADC: C19.1 R16.1 R17.2 U1.2(P6.1/CB1/A1)
EZFET_D_N: C11.1 R4.2 U1.52(PU.1/DM)
EZFET_D_P: C12.1 R5.2 R6.2 R7.1 U1.50(PU.0/DP)
EZFET_LED0: R1.2 U1.20(P1.2/TA0.1)
EZFET_LED1: R2.2 U1.21(P1.3/TA0.2)
EZFET_PUR: R7.2 U1.51(PUR)
EZFET_RST: C24.1 J2.11 R19.1 U1.64(~{RST}/NMI/SBWTDIO)
EZFET_TCK: J2.7 U1.63(PJ.3/TCK)
EZFET_TDI: J2.3 U1.61(PJ.1/TDI/TCLK)
EZFET_TDO: J2.1 U1.60(PJ.0/TDO)
EZFET_TEST: J2.8 U1.59(TEST/SBWTCK)
EZFET_TMS: J2.5 U1.62(PJ.2/TMS)
EZFET_UARTRXD: R10.1 U1.38(P3.4/UCA0RXD/UCA0SOMI)
EZFET_UARTTXD: R11.1 U1.37(P3.3/UCA0TXD/UCA0SIMO)
EZFET_USB_Shield: C5.1 J1.6 J1.7 J1.8 J1.9 J1.10 J1.11 R3.2
EZFET_V18: C2.1 U1.55(V18)
EZFET_VCORE: C3.1 U1.17(VCORE)
EZFET_VREF: C1.1 U1.9(P5.0/A8/VREF+/VEREF+)
EZFET_VUSB: C4.1 U1.54(VUSB)
EZFET_XT2IN: U1.57(P5.2/XT2IN) Y1.1(In)
EZFET_XT2OUT: U1.58(P5.3/XT2OUT) Y1.3(Out)
MCU_UARTRXD: J3.8 ; off-sheet MCU_UARTRXD
MCU_UARTTXD: J3.6 ; off-sheet MCU_UARTTXD
RST/SBWTDIO: J3.4 ; off-sheet RST/SBWTDIO
T_RST_RST: R9.1 U1.43(P4.2/PM_UCB1SOMI/PM_UCB1SCL)
T_TEST_TCKC: R8.1 U1.44(P4.3/PM_UCB1CLK/PM_UCA1STE)
TST/SBWTCK: J3.2 ; off-sheet TST/SBWTCK
USB_D_N: J1.2(D-) R4.1 U2.3(IO1)
USB_D_P: J1.3(D+) R5.1 U2.2(NC) U2.5(NC) U2.6(IO2)
NetC16_2: C16.2 J3.1 R8.2
NetC17_2: C17.2 J3.3 R9.2
NetC20_1: C20.1 U3.2(NR)
NetC21_1: C21.1 C22.1 R18.1 U3.1(OUT)
NetD1_2: D1.2(A) R1.1
NetD2_2: D2.2(A) R2.1
NetJ1_1: J1.1(VBUS) L1.1
NetJ1_5: J1.5(GND) L2.1
NetJ2_2: J2.2 R13.2
NetJ2_4: J2.4 R12.2
NetJ3_5: J3.5 R10.2
NetJ3_7: J3.7 R11.2

Not connected (* = marked no-connect by the designer): J1 4(ID)*; J2 6* 10* 12* 13* 14*; J3 11* 12*; U1 3(P6.2/CB2/A2)* 4(P6.3/CB3/A3)* 5(P6.4/CB4/A4)* 6(P6.5/CB5/A5)* 7(P6.6/CB6/A6)* 8(P6.7/CB7/A7)* 10(P5.1/A9/VREF-/VEREF-)* 12(P5.4/XIN)* 13(P5.5/XOUT)* 18(P1.0/TA0CLK/ACLK)* 19(P1.1/TA0.0)* 22(P1.4/TA0.3)* 23(P1.5/TA0.4)* 24(P1.6/TA1CLK/CBOUT)* 25(P1.7/TA1.0)* 26(P2.0/TA1.1)* 27(P2.1/TA1.2)* 28(P2.2/TA2CLK/SMCLK)* 29(P2.3/TA2.0)* 30(P2.4/TA2.1)* 31(P2.5/TA2.2)* 32(P2.6/RTCCLK/DMAE0)* 33(P2.7/UCB0STE/UCA0CLK)* 34(P3.0/UCB0SIMO/UCB0SDA)* 35(P3.1/UCB0SOMI/UCB0SCL)* 36(P3.2/UCB0CLK/UCA0STE)* 41(P4.0/PM_UCB1STE/PM_UCA1CLK)* 42(P4.1/PM_UCB1SIMO/PM_UCB1SDA)* 45(P4.4/PM_UCA1TXD/PM_UCA1SIMO)* 46(P4.5/PM_UCA1RXD/PM_UCA1SOMI)* 47(P4.6/PM_NONE)* 48(P4.7/PM_NONE)*

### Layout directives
net class Power-Net: EZFET_VBUS, EZFET_VCC, GND, VCC
differential pair: EZFET_D_N, EZFET_D_P, USB_D_N, USB_D_P

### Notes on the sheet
- (near D1) Host MCU for Emulation
- (near C23) Place near MSP430
- (near C18) to Host-MCU
- to Target-Connector
- to Voltage-Divider
- (near R19) Reset Circuit
- to USB
- to TAG-Connector
- (near U3) TPS773533: 3.3V, 500mA
- JTAG-Connector (Host Debug)
- (near J2) Host-MCU Debug Connector
- USB-Interface
- POP R13 if FET is supplying 3V3 to MSP430
  POP R12 if USB is supplying 3V3 to MSP430 (via LDO)
- (near SH-J1) Shunts for J7
- to Host-MCU
- Target Connector
- to Target
- to Target MCU

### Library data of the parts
C1 C14 = CMP-0006221-2: CAP, CERM, 0.1 uF, 10 V, +/- 20%, X5R, 0402; Manufacturer: Wurth Elektronik; TaMin_C: -55°C; Polarized: N; SizeAreaWB_mm2: 3; Value1: Unknown; U/M: EA; Value: 0.1uF; TaMax_C: 85°C; SizeZ_mm: 0.6; SizeX_mm: 1; SizeY_mm: 0.5; Cap_Case: 0402; Cap_F: 100nF; AEC Category: Q200
C2 C4 C5 = CMP-0078875-1: CAP, CERM, 0.22 µF, 10 V,+/- 20%, X5R, 0402; Manufacturer: Wurth Elektronik; TaMin_C: -55°C; Polarized: N; SizeAreaWB_mm2: 3; U/M: EA; Value: 0.22uF; TaMax_C: 85°C; SizeZ_mm: 0.6; SizeX_mm: 1; SizeY_mm: 0.5; Cap_Case: 0402; Cap_F: 220nF; AEC Category: Q200
C3 = CMP-0006600-2: CAP, CERM, 0.47 uF, 16 V, +/- 10%, X5R, 0402; Manufacturer: MuRata; TaMin_C: -55°C; Polarized: N; SizeAreaWB_mm2: 3; Value1: Unknown; U/M: EA; Value: 0.47uF; TaMax_C: 85°C; SizeZ_mm: 0.6; SizeX_mm: 1; SizeY_mm: 0.5; Cap_Case: 0402; Cap_F: 470nF; AEC Category: Q200
C6 = CMP-0084376-1: CAP, Tantalum Polymer, 10 µF, 10 V,+/- 20%, 0.08 ohm, 3216-18 SMD; Manufacturer: Kemet; TaMin_C: -55°C; SizeArea_mm2: 5.12; Value: 10uF; SizeAreaWB_mm2: 10.92; SizeY_mm: 1.6; Polarized: Y; SizeX_mm: 3.2; AEC Qualified: N; TaMax_C: 105°C; SizeZ_mm: 1.8; ESR_ohm: 0.08; CompType: Capacitor; AEC Category: Q200
C7 C8 C10 = CMP-0064931-4: CAP, CERM, 0.1 uF, 10 V,+/- 10%, X7R, 0603; Manufacturer: Wurth Elektronik; TaMin_C: -55°C; Polarized: N; SizeAreaWB_mm2: 4.68; Value1: Unknown; U/M: EA; Value: 0.1uF; TaMax_C: 125°C; SizeZ_mm: 1; SizeX_mm: 1.6; SizeY_mm: 0.8; Cap_Case: 0603; SizeArea_mm2: 1.28; AEC Category: Q200
C9 = CMP-0090362-1: 0.1µF ±10% 10V Ceramic Capacitor X7R 0402 (1005 Metric); Manufacturer: Wurth Electronics; AEC Qualified: No; Value: 100nF; SizeZ_mm: 0.55mm; TempCo: 15%
C11 C12 C16 C17 = CMP-0006215-2: CAP, CERM, 10 pF, 50 V, +/- 5%, C0G/NP0, 0402; Manufacturer: Wurth Elektronik; TaMin_C: -55°C; Polarized: N; SizeAreaWB_mm2: 3; Value1: Unknown; U/M: EA; Value: 10pF; TaMax_C: 125°C; SizeZ_mm: 0.6; SizeX_mm: 1; SizeY_mm: 0.5; Cap_Case: 0402; AEC Category: Q200
C13 C22 = CMP-0064924-2: CAP, CERM, 1 uF, 10 V,+/- 20%, X5R, 0402; Manufacturer: Wurth Elektronik; TaMin_C: -55°C; Polarized: N; SizeAreaWB_mm2: 3; Value1: Unknown; U/M: EA; Value: 1uF; TaMax_C: 85°C; SizeZ_mm: 0.6; SizeX_mm: 1; SizeY_mm: 0.5; Cap_Case: 0402; Cap_F: 1µF; AEC Category: Q200
C15 C20 = CMP-0006227-2: CAP, CERM, 0.01 uF, 16 V, +/- 10%, X7R, 0402; Manufacturer: Wurth Elektronik; TaMin_C: -55°C; Polarized: N; SizeAreaWB_mm2: 3; Value1: Unknown; U/M: EA; Value: 0.01uF; TaMax_C: 125°C; SizeZ_mm: 0.6; SizeX_mm: 1; SizeY_mm: 0.5; Cap_Case: 0402; Cap_F: 10nF; AEC Category: Q200
C18 C19 = CMP-0006250-2: CAP, CERM, 33 pF, 50 V, +/- 5%, C0G/NP0, 0402; Manufacturer: TDK; TaMin_C: -55°C; Polarized: N; SizeAreaWB_mm2: 3; Value1: Unknown; U/M: EA; Value: 33pF; TaMax_C: 125°C; SizeZ_mm: 0.6; SizeX_mm: 1; SizeY_mm: 0.5; Cap_Case: 0402; AEC Category: Q200
C21 = CMP-0006222-2: CAP, CERM, 2.2 uF, 10 V, +/- 20%, X5R, 0402; Manufacturer: Wurth Elektronik; TaMin_C: -55°C; Polarized: N; SizeAreaWB_mm2: 3; Value1: Unknown; U/M: EA; Value: 2.2uF; TaMax_C: 85°C; SizeZ_mm: 0.6; SizeX_mm: 1; SizeY_mm: 0.5; Cap_Case: 0402; Cap_F: 2.2µF; AEC Category: Q200
C23 = CMP-0006269-2: CAP, CERM, 4.7 uF, 10 V, +/- 20%, X5R, 0402; Manufacturer: TDK; TaMin_C: -55°C; Polarized: N; SizeAreaWB_mm2: 3; Value1: Unknown; U/M: EA; Value: 4.7uF; TaMax_C: 85°C; SizeZ_mm: 0.6; SizeX_mm: 1; SizeY_mm: 0.5; Cap_Case: 0402; Cap_F: 4.7µF; AEC Category: Q200
C24 = CMP-0006231-2: CAP, CERM, 1000 pF, 50 V, +/- 10%, X7R, 0402; Manufacturer: Wurth Elektronik; TaMin_C: -55°C; Polarized: N; SizeAreaWB_mm2: 3; Value1: Unknown; U/M: EA; Value: 1000pF; TaMax_C: 125°C; SizeZ_mm: 0.6; SizeX_mm: 1; SizeY_mm: 0.5; Cap_Case: 0402; Cap_F: 1nF; AEC Category: Q200
C25 = CMP-0006562-2: CAP, CERM, 0.1 uF, 10 V, +/- 10%, X5R, 0402; Manufacturer: MuRata; TaMin_C: -55°C; Polarized: N; SizeAreaWB_mm2: 3; Value1: Unknown; U/M: EA; Value: 0.1uF; TaMax_C: 85°C; SizeZ_mm: 0.6; SizeX_mm: 1; SizeY_mm: 0.5; Cap_Case: 0402; Cap_F: 100nF; AEC Category: Q200
D1 = CMP-0002947-3: LED, Red, SMD; Manufacturer: Wurth Elektronik; Type: AlInGaP; Vf_V: 2V; Io_A: 30mA; Vr_V: 5V; Tjmax_C: 85°C; Power_TotalModule: 72mW; Value1: 0.072W; Angle: 140
D2 = CMP-0002894-2: LED, Green, SMD; Manufacturer: Wurth Elektronik; PartNumber: 150060VS75000; Type: AlInGaP; Vf_V: 2V; Io_A: 20mA; Value1: W
J1 = CMP-0055311-1: Receptacle, USB 2.0, Micro B, 5 Position, R/A, SMT; PartNumber: 1051640001; Manufacturer: Molex; Pitch_mm: 0.65; Gender: Female; ContactFinish: Gold; Current_A: 1.8A; Voltage_V: 30V; Cert_UL: Y; CNHeader: FALSE; CT: TRUE
J2 J3 = CMP-0086014-1: Header, 2.54mm, 7x2, Gold, TH; Manufacturer: Wurth Elektronik; Pitch_mm: 2.54; Voltage_V: 250V; Shrouded: N; Gender: Male; Current_A: 3A; Cert_UL: Y; Row_Count: 2
L1 L2 = CMP-0003184-2: Ferrite Bead, 140 ohm @ 100 MHz, 0.55 A, 0603; Manufacturer: Wurth Elektronik; Ztyp@1GHz_Ohm: 271.401; ZTyp@100MHz_Ohm: 140; SizeAreaWB_mm2: 4.68; DCR_ohm: 0.2; Value1: 0.2 ohm; Value: 140 ohm; Imax_A: 550mA; SizeZ_mm: 1; SizeX_mm: 1.6; SizeY_mm: 0.8; Value2: 0.55A; SizeArea_mm2: 1.28
R1 = CMP-0026934-3: RES, 470, 5%, 0.063 W, AEC-Q200 Grade 0, 0402; Manufacturer: Vishay-Dale; Value: 470; Value_Code: 470R; Power_W: 63mW; Value2: 0.063W; VDC_V: 50V; TempCo: 200 ppm/C; SizeArea_mm2: 0.5; SizeX_mm: 1; SizeZ_mm: 0.6; EIA_Code: E24; AEC Category: Q200; AEC Qualified: Y; AEC Grade: 0
R2 = CMP-0026914-3: RES, 390, 5%, 0.063 W, AEC-Q200 Grade 0, 0402; Manufacturer: Vishay-Dale; Value: 390; Value_Code: 390R; Power_W: 63mW; Value2: 0.063W; VDC_V: 50V; TempCo: 200 ppm/C; SizeArea_mm2: 0.5; SizeX_mm: 1; SizeZ_mm: 0.6; EIA_Code: E24; AEC Category: Q200; AEC Qualified: Y; AEC Grade: 0
R3 = CMP-0026907-3: RES, 33 k, 5%, 0.063 W, AEC-Q200 Grade 0, 0402; Manufacturer: Vishay-Dale; Power_W: 63mW; TempCo: 200 ppm/C; Value_Code: 33k0; Value: 33k; EIA_Code: E24; SizeX_mm: 1; SizeY_mm: 0.5; SizeZ_mm: 0.6; Value2: 0.063W; AEC Qualified: Y; VDC_V: 50V; AEC Category: Q200; AEC Grade: 0
R4 R5 = CMP-0026888-3: RES, 27, 5%, 0.063 W, AEC-Q200 Grade 0, 0402; Manufacturer: Vishay-Dale; Power_W: 63mW; TempCo: 200 ppm/C; Value_Code: 27R0; Value: 27; EIA_Code: E24; SizeX_mm: 1; SizeY_mm: 0.5; SizeZ_mm: 0.6; Value2: 0.063W; AEC Qualified: Y; VDC_V: 50V; AEC Category: Q200; AEC Grade: 0
R6 = CMP-0026859-2: RES, 1.0 M, 5%, 0.063 W, AEC-Q200 Grade 0, 0402; Manufacturer: Vishay-Dale; Power_W: 63mW; TempCo: 200 ppm/C; Value_Code: 1M00; Value: 1.0Meg; EIA_Code: E24; Res_ohm: 1M; SizeX_mm: 1; SizeY_mm: 0.5; SizeZ_mm: 0.6; Value2: 0.063W; AEC Qualified: Y; VDC_V: 50V; AEC Category: Q200; AEC Grade: 0
R7 = CMP-0026085-3: RES, 1.40 k, 1%, 0.063 W, AEC-Q200 Grade 0, 0402; Manufacturer: Vishay-Dale; Power_W: 63mW; TempCo: 100 ppm/C; Value_Code: 1k40; Value: 1.40k; EIA_Code: E96; Res_ohm: 1.4k; SizeX_mm: 1; SizeY_mm: 0.5; SizeZ_mm: 0.6; Value2: 0.063W; AEC Qualified: Y; VDC_V: 50V; AEC Category: Q200; AEC Grade: 0
R8-R11 = CMP-0025963-3: RES, 10.0, 1%, 0.063 W, AEC-Q200 Grade 0, 0402; Manufacturer: Vishay-Dale; Power_W: 63mW; TempCo: 100 ppm/C; Value_Code: 10R0; Value: 10.0; EIA_Code: E96; Res_ohm: 10; SizeX_mm: 1; SizeY_mm: 0.5; SizeZ_mm: 0.6; Value2: 0.063W; AEC Qualified: Y; VDC_V: 50V; AEC Category: Q200; AEC Grade: 0
R12 R13 = CMP-0026992-3: RES, 0, 5%, 0.1 W, AEC-Q200 Grade 0, 0402; Manufacturer: Panasonic; Value_Code: 0000; Power_W: 100mW; Value2: 0.1W; VDC_V: 50V; TempCo: 600 ppm/C; EIA_Code: E24; AEC Category: Q200; AEC Qualified: Y; SizeArea_mm2: 0.5; SizeAreaWB_mm2: 3; SizeX_mm: 1; SizeZ_mm: 0.6
R14 = CMP-0026190-2: RES, 240 k, 1%, 0.063 W, AEC-Q200 Grade 0, 0402; Manufacturer: Vishay-Dale; Power_W: 63mW; TempCo: 100 ppm/C; Value: 240k; SizeX_mm: 1; SizeY_mm: 0.5; SizeZ_mm: 0.6; Value2: 0.063W; AEC Qualified: Y; VDC_V: 50V; AEC Category: Q200; AEC Grade: 0
R15 = CMP-0026021-3: RES, 150 k, 1%, 0.063 W, AEC-Q200 Grade 0, 0402; Manufacturer: Vishay-Dale; Power_W: 63mW; TempCo: 100 ppm/C; Value: 150k; EIA_Code: E96; SizeX_mm: 1; SizeY_mm: 0.5; SizeZ_mm: 0.6; Value2: 0.063W; AEC Qualified: Y; VDC_V: 50V; AEC Category: Q200; AEC Grade: 0
R16 R17 = CMP-0026728-1: RES, 220 k, 1%, 0.0625 W, 0402; Manufacturer: Yageo America; Power_W: 62.5mW; TempCo: 100 ppm/C; U/M: EA; Value: 220k; SizeX_mm: 1; SizeY_mm: 0.5; SizeZ_mm: 0.6; AEC Qualified: N; VDC_V: 50V; AEC Category: Q200
R18 = CMP-0081856-1: RES, 0, 0%, 0.2 W, AEC-Q200 Grade 0, 0402; Manufacturer: Vishay-Dale; SizeAreaWB_mm2: 3; SizeArea_mm2: 0.5; AEC Qualified: Y; AEC Category: Q200; Value: 0; SizeZ_mm: 0.6; Power_W: 200mW; VDC_V: 50V; Value2: 0.2W; SizeX_mm: 1
R19 = CMP-0026935-3: RES, 47 k, 5%, 0.063 W, AEC-Q200 Grade 0, 0402; Manufacturer: Vishay-Dale; Power_W: 63mW; TempCo: 200 ppm/C; Value_Code: 47k0; Value: 47k; EIA_Code: E24; SizeX_mm: 1; SizeY_mm: 0.5; SizeZ_mm: 0.6; Value2: 0.063W; AEC Qualified: Y; VDC_V: 50V; AEC Category: Q200; AEC Grade: 0
SH-J1-SH-J6 = CMP-0003761-2: as SH-J7 on sheet MD063A_Sch
U1 = CMP-0039269-4: 16-Bit Ultra-Low-Power Microcontroller, 128KB Flash, 8KB RAM, USB, 12Bit ADC, 2 USCIs, 32Bit HW MPY, RGC0064B (VQFN-64); Alternate Manufacturer: Texas Instruments; Alternate PartNumber: MSP430F5528IRGCR; ADC: 12-bit SAR; ADC Channels: 16; Brown Out Reset: Yes; DMA: 3; Flash(KB): 128; Frequency(MHz): 25; GPIO: 47; Multiplier: 32x32; SRAM(B): 8192; Timers - 16-bit: 4; USB: 1; USCI_A (UART/LIN/IrDA/SPI): 2; Rating: Catalog; SizeArea_mm2: 81.0; SizeZ_mm: 1.0; Green_REACh: Passed; AEC Qualified: N; AEC Category: Q200; CompType: IC; Green_Lifecycle: Active; SizeY_mm: 9.0; SizeAreaWB_mm2: 121.0
U2 = CMP-0043099-3: Low-Capacitance 2-Channel +/-15kV ESD Protection Array for High-Speed Data Interfaces, DRY0006A (USON-6); Manufacturer: Texas Instruments; IO Leakage Current(nA): 1; IEC 61000-4-2 Air-Gap(+/- kV): 15; USB High Speed: TRUE; IO Capacitance(Typ)(pF): 1.5; Eco-Plan: Green (RoHS & no Sb/Br); Breakdown Voltage(Min)(V): 11; IEC 61000-4-2 Contact(+/- kV): 8; AEC Category: Q200; AEC Qualified: N; CompType: IC; SizeAreaWB_mm2: 4.9; SizeArea_mm2: 1.45; SizeX_mm: 1.0; SizeZ_mm: 0.6; Rating: Catalog
U3 = CMP-0036330-5: Single Output High PSRR LDO, 500 mA, Fixed 3.3 V Output, 2.7 to 6.5 V Input, with Low IQ, 6-pin SON (DRV), -40 to 125 degC, Green (RoHS & no Sb/Br); Manufacturer: Texas Instruments; SubFamily: Single Channel LDO; Vin(Max)(V): 6.5; Vin(Min)(V): 2.7; Iout(Max)(A): 0.5; Iq(Typ)(mA): 0.04; Fixed Output Options(V): 3.3; Vdo(Typ)(mV): 280; Accuracy(%): 2; CompType: IC; SizeAreaWB_mm2: 9; SizeArea_mm2: 4; SizeZ_mm: 0.8
Y1 = CMP-0085483-1: Oscillator, 4 MHz, 700 ppm, 39 pF, SMD; Manufacturer: MuRata; SizeArea_mm2: 9; Load Capacitance: 39 pF; SizeZ_mm: 1.2; AEC Category: Q200; Frequency Tolerance: 700 ppm; SizeX_mm: 4.5; SizeAreaWB_mm2: 16.5; TaMax_C: 85°C; TaMin_C: -20°C; SizeY_mm: 2; AEC Qualified: N; Frequency_Fixed: 4MHz

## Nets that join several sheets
GND: MD063A_Sch (39 pins), ezFET (46 pins)
VCC: MD063A_Sch (14 pins), ezFET (J3.10)
MCU_UARTRXD: MD063A_Sch (U5.3), ezFET (J3.8)
MCU_UARTTXD: MD063A_Sch (U5.4), ezFET (J3.6)
RST/SBWTDIO: MD063A_Sch (C35.1 J5.1 R23.1 U5.24), ezFET (J3.4)
TST/SBWTCK: MD063A_Sch (U5.25), ezFET (J3.2)

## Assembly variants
001: not fitted C26 C32 C34 C36 C37 C38 C39 C40 C41 C42 R12 R20 R21 R22 U4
